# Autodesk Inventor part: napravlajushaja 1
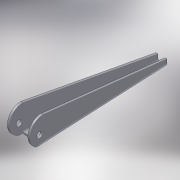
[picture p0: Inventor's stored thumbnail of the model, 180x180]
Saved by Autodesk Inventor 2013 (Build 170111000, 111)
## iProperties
Shininess: 25.0
Length Units: 11269
Angle Units: 11279
Time Units: 11290
Mass Units: 11283
Length Display Precision: 3
Angle Display Precision: 2
Created: 2002-03
Part Number: napravlajushaja 1
Material: Steel, Mild
Document SubType Name: Modeling
Designer: =<Author>
Density: 7.86 g/cm^3
Description: =<Part Number>
Density: 7.86
Volumn: 14.555006472310083
Area: 154.8804738042341
PropertySet Name: Model Information
Control State: 0
Master: False
Checked Out: True
Last Check In Date: 2008-10-15
Checked Out Date: 2008-10-15
Author: LAlexey
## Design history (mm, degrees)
sketch "Sketch1"
  geometry: L1 (-85.87, -95.944)-(-79.62, 43.056); L2 (-79.62, 43.056)-(-68.12, 43.056); L3 (-68.12, 43.056)-(-61.87, -95.944); L4 (-61.87, -95.944)-(-85.87, -95.944)
  constraints: 8 end point, 1 equal length, 1 horizontal, 1 parallel
  dimensions: "d7" = 139 distance between parallel lines of L4 L2; "d8" = 11.5 distance of L1.end L2.end; "d9" = 24 distance of L3.end L1.start
extrude "Extrusion1" new body sketch "Sketch1" distance "d10" = 2; taper "d11" = 0 deg
sketch "Sketch2"
  geometry: L1 (2, 0)-(2, 139.14) reference; L2 (0, 0)-(2, 0) reference; L3 (2, 139.14)-(8, 139.14); L4 (8, 139.14)-(29, 0); L5 (29, 0)-(2, 0)
  constraints: 6 end point, 1 parallel, 1 perpendicular
  dimensions: "d12" = 27 distance of L4.end L1.start; "d13" = 6 distance of L1.end L3.end
extrude "Extrusion2" join sketch "Sketch2" distance "d14" = 2; taper "d15" = 0 deg
sketch "Sketch3"
  geometry: L1 (-2, 139.14)-(-2, 0) reference; L2 (0, 139.14)-(-2, 139.14) reference; L3 (-2, 139.14)-(-8, 139.14); L4 (-8, 139.14)-(-29, 0); L5 (-2, 0)-(-29, 0)
  constraints: 6 end point, 1 collinear, 1 parallel
  dimensions: "d16" = 27 distance of L1.end L4.end; "d17" = 6 distance of L1.start L3.end
extrude "Extrusion3" join sketch "Sketch3" distance "d18" = 2; taper "d19" = 0 deg
workplane "Work Plane1"
workplane "Work Plane2"
sketch "Sketch4"
  geometry: L1 (0, -29)-(-139, -29) reference; L2 (-139, -21)-(0, 0) reference; L3 (0, -29)-(0, 0); L4 (0, -27)-(-138.91, -27) reference; C1 r 3 at (4, -17); A1 r 14.5 centre (0, -14.5) between (0, -29) and (0, 0)
  constraints: 2 centre point, 2 end point, 2 point on circle, 1 perpendicular, 1 tangent
  dimensions: "d24" = 6 diameter of C1; "d25" = 12 distance from line of L1 C1.centre; "d28" = 4 distance from line of C1.centre L3
extrude "Extrusion4" join sketch "Sketch4" stored distance "d29" = 2; taper "d30" = 0 deg
sketch "Sketch5"
  geometry: L1 (85.87, -95.944)-(61.87, -95.944) reference; L2 (85.87, -95.944)-(85.87, -110.444) reference; L3 (61.87, -95.944)-(61.87, -110.444) reference; L4 (85.87, -95.944)-(61.87, -95.944); L5 (63.87, -124.722)-(83.87, -125.333); L6 (83.87, -95.944)-(83.87, -125.333); L7 (63.87, -95.944)-(63.87, -124.722)
  constraints: 8 end point, 2 point on line, 1 collinear, 1 parallel, 1 perpendicular
  dimensions: "d31" = 2 distance between parallel lines of L2 L6; "d32" = 2 distance between parallel lines of L3 L7
extrude "Extrusion5" cut sketch "Sketch5" distance "d33" = 200; taper "d34" = 0 deg
fillet "Fillet1" dims "d35" = 2
fillet "Fillet2" dims "d36" = 4
sketch "Sketch6"
  geometry: L1 (72.124, 43.056)-(75.616, 43.056) reference; L2 (61.87, -95.944)-(61.87, -110.444) reference; C1 r 2 at (73.87, 3.556); 1 further point
  constraints: 1 centre point
  dimensions: "d37" = 37.5 distance edge to line of C1 L1; "d38" = 4 diameter of C1; "d39" = 12 distance from line of L2 C1.centre
extrude "Extrusion6" cut sketch "Sketch6" distance "d40" = 200; taper "d41" = 0 deg
body "Solid1"
other parameters: "d20" = 90 deg, "d21" = 90 deg, "d22" = 0, "d23" = 0
